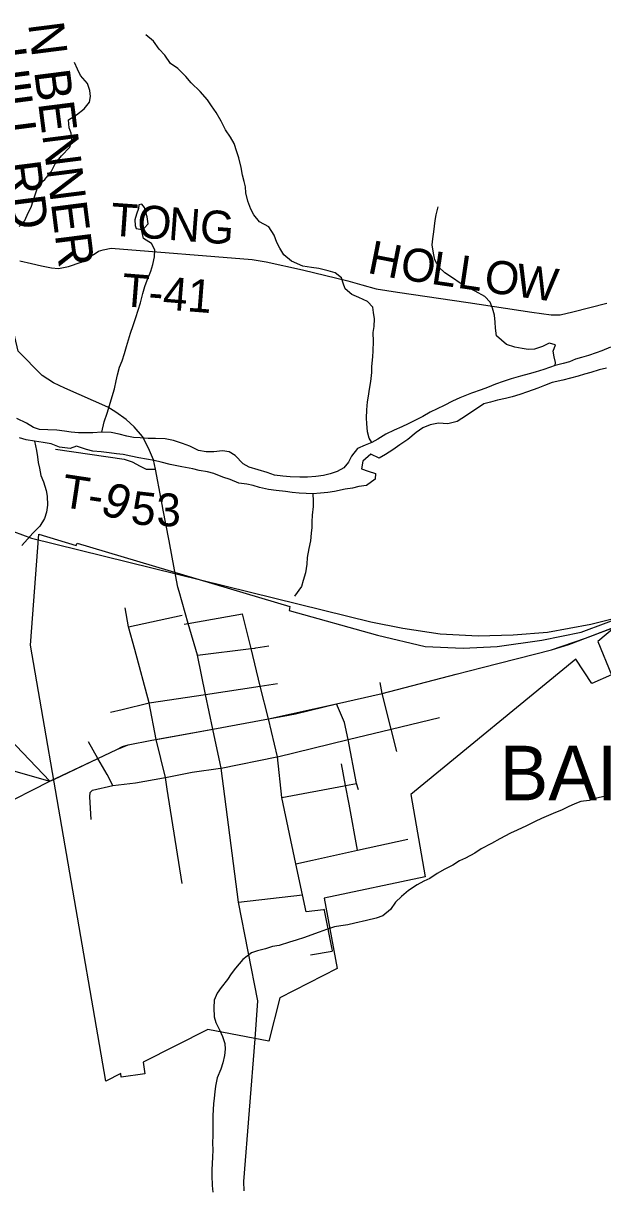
# Model space of a CAD drawing. Extents: x -139 to 835, y 0 to 440.
# Drawn here: x 462.8 to 494.5, y 270.4 to 334.2 of the extents above; entities that cross this region are included whole.
import ezdxf

# ---------------------------------------------------------------- set-up
doc = ezdxf.new("R2010")
doc.units = 0
for name, color, linetype in [('Default', 7, 'Continuous'), ('GM_X_City_Street', 7, 'Continuous'), ('GM_X_Corporation', 7, 'Continuous'), ('GM_X_Corporation_Text', 7, 'Continuous'), ('GM_X_County_Road', 7, 'Continuous'), ('GM_X_Major_River', 7, 'Continuous'), ('GM_X_Minor_Lake', 7, 'Continuous'), ('GM_X_Minor_River', 7, 'Continuous'), ('GM_X_Rail_Line', 7, 'Continuous'), ('GM_X_State_Route', 7, 'Continuous'), ('GM_X_Township_Road', 7, 'Continuous'), ('GM_X_Township_Road_Text', 7, 'Continuous'), ('GM_X_US_Route', 7, 'Continuous'), ('SH_Text', 7, 'Continuous')]:
    doc.layers.add(name, color=color, linetype=linetype)

msp = doc.modelspace()

# ---------------------------------------------------------------- linework, layer by layer
at = {"layer": 'Default'}
for p, q in [((493.599, 300.491), (496.955, 301.767)), ((491.732, 299.847), (493.599, 300.491)), ((493.599, 300.491), (493.599, 300.491)), ((487.937, 298.879), (491.732, 299.847)), ((482.445, 297.453), (486.513, 298.509)), ((486.513, 298.509), (487.937, 298.879)), ((479.94, 296.881), (482.445, 297.453)), ((476.205, 296.063), (479.94, 296.881)), ((473.155, 295.495), (476.205, 296.063)), ((469.81, 294.894), (473.155, 295.495)), ((467.886, 294.389), (468.504, 294.643)), ((468.504, 294.643), (469.81, 294.894)), ((464.221, 292.642), (466.851, 293.897)), ((466.851, 293.897), (467.886, 294.389))]:
    msp.add_line(p, q, dxfattribs=at)
at = {"layer": 'GM_X_City_Street'}
for p, q in [((468.537, 301.111), (471.478, 301.759)), ((475.525, 299.955), (476.231, 300.065)), ((467.542, 296.424), (468.186, 296.579)), ((473.56, 293.615), (473.155, 295.495)), ((471.468, 287.037), (470.652, 292.215)), ((481.092, 288.858), (480.628, 291.386)), ((477.71, 288.118), (478.632, 288.32)), ((474.568, 286.013), (478.072, 286.417)), ((478.272, 285.474), (478.072, 286.417))]:
    msp.add_line(p, q, dxfattribs=at)
for points in [[(468.873, 299.87), (468.537, 301.111), (468.354, 302.157)], [(471.591, 301.266), (471.811, 301.304), (474.792, 301.82)], [(478.072, 286.417), (477.71, 288.118), (476.934, 291.761), (476.699, 293.979), (476.205, 296.063), (475.762, 297.866), (475.258, 299.92), (474.792, 301.82)], [(470.652, 292.215), (470.552, 292.848), (470.045, 294.939), (469.666, 296.937), (468.873, 299.87)], [(472.311, 299.562), (475.258, 299.92), (475.454, 299.944), (475.525, 299.955)], [(468.186, 296.579), (469.666, 296.937), (472.758, 297.408), (475.762, 297.866), (476.702, 298.01)], [(483.245, 294.283), (482.939, 295.497), (482.445, 297.453), (482.331, 298.06)], [(481.151, 292.168), (481.047, 292.517), (480.588, 294.932), (480.385, 295.865), (479.94, 296.881)], [(473.58, 293.36), (473.615, 293.364), (476.677, 293.974), (476.699, 293.979), (480.588, 294.932), (482.939, 295.497), (485.586, 296.134)], [(466.482, 290.547), (466.41, 291.781), (466.42, 292.027), (466.549, 292.154), (467.674, 292.408), (467.36, 293.009), (466.851, 293.897), (466.327, 294.812)], [(470.449, 292.829), (470.552, 292.848), (472.028, 293.144), (473.58, 293.36)], [(475.472, 278.515), (475.617, 280.609), (474.568, 286.013), (473.615, 293.364), (473.56, 293.615)], [(480.628, 291.386), (480.441, 292.405), (480.222, 293.598)], [(467.674, 292.408), (468.907, 292.55), (470.449, 292.829)], [(476.934, 291.761), (480.361, 292.391), (480.441, 292.405), (481.047, 292.517)], [(478.632, 288.32), (481.092, 288.858), (483.86, 289.463)], [(478.508, 283.13), (479.702, 283.33), (479.72, 283.36), (479.706, 283.429), (479.306, 285.472), (479.286, 285.576), (479.272, 285.605), (479.235, 285.6), (478.272, 285.474)]]:
    msp.add_lwpolyline(points, dxfattribs=at)
at = {"layer": 'GM_X_Corporation'}
msp.add_lwpolyline([(472.881, 279.036), (469.327, 277.229), (469.425, 276.595), (468.135, 276.408), (468.104, 276.611), (467.284, 276.194), (463.155, 300.109), (463.618, 306.188), (465.65, 305.582), (465.706, 305.704), (477.378, 302.223), (477.35, 302.012), (482.189, 300.655), (484.807, 300.027), (486.895, 299.935), (488.75, 300.036), (491.21, 300.383), (493.37, 300.818), (496.112, 301.837), (494.271, 300.317), (495.033, 298.472), (493.952, 298.002), (493.067, 299.334), (484.022, 291.91), (484.801, 287.395), (479.266, 286.223), (479.982, 282.368), (476.832, 280.77), (476.231, 278.382)], close=True, dxfattribs=at)
at = {"layer": 'GM_X_County_Road'}
msp.add_lwpolyline([(474.878, 270.188), (474.866, 270.692), (475.472, 278.515)], dxfattribs=at)
at = {"layer": 'GM_X_Major_River'}
for points in [[(494.98, 316.457), (494.507, 316.258), (494.179, 316.142), (493.759, 315.99), (493.379, 315.886), (493.051, 315.794), (492.723, 315.653), (492.369, 315.561), (491.937, 315.446), (491.32, 315.225), (490.847, 315.074), (490.52, 314.982), (490.035, 314.867), (489.524, 314.716), (489.091, 314.565), (488.671, 314.414), (488.224, 314.239), (487.883, 314.11), (487.345, 313.924), (486.715, 313.679), (486.307, 313.492), (485.847, 313.257), (485.084, 312.881), (484.676, 312.645), (484.308, 312.457), (483.874, 312.246), (483.533, 312.082), (483.099, 311.895), (482.652, 311.683), (482.217, 311.412), (481.875, 311.224), (481.521, 311.084), (481.087, 310.897), (480.768, 310.48), (480.607, 310.146), (480.341, 309.837), (479.973, 309.637), (479.592, 309.497), (479.225, 309.417), (478.807, 309.349), (478.349, 309.33), (477.931, 309.323), (477.396, 309.341), (477.005, 309.369), (476.536, 309.434), (476.146, 309.583), (475.639, 309.72), (475.158, 309.869), (474.821, 310.053), (474.383, 310.502), (474.046, 310.71), (473.681, 310.762), (473.211, 310.707)], [(494.755, 315.295), (494.349, 315.204), (493.89, 315.065), (493.549, 314.972), (493.195, 314.856), (492.776, 314.753), (492.356, 314.637), (491.78, 314.512), (491.347, 314.348), (490.979, 314.208), (490.415, 313.999), (489.995, 313.859), (489.575, 313.732), (489.208, 313.64), (488.776, 313.536), (488.383, 313.433), (488.029, 313.341), (487.067, 312.703)], [(473.211, 310.707), (472.793, 310.711), (472.363, 310.776), (471.896, 311.021), (471.493, 311.17), (470.999, 311.331), (470.544, 311.42), (470.008, 311.438), (469.604, 311.443), (469.173, 311.471), (468.808, 311.499), (468.43, 311.575), (468.027, 311.688), (467.584, 311.765), (467.075, 311.782), (466.579, 311.752), (466.134, 311.745), (465.795, 311.748), (465.378, 311.789), (465.013, 311.853), (464.596, 311.906), (464.1, 311.911), (463.656, 311.928), (463.318, 312.052), (462.93, 312.284), (462.411, 312.542)], [(487.067, 312.703), (486.566, 312.373), (486.042, 312.246), (485.546, 312.276), (485.088, 312.185), (484.681, 312.033), (484.312, 311.773), (483.849, 311.394), (483.414, 311.087), (483.032, 310.815), (482.637, 310.567), (482.281, 310.367), (481.827, 310.576), (481.378, 310.197), (481.307, 309.778), (481.671, 309.642), (482.074, 309.53), (482.069, 309.206), (481.581, 308.863), (481.176, 308.807), (480.822, 308.727), (480.417, 308.672), (479.84, 308.534), (479.461, 308.478), (479.068, 308.446), (478.65, 308.415), (478.285, 308.431), (477.893, 308.447), (477.515, 308.475), (477.137, 308.528), (476.628, 308.581), (476.211, 308.646), (475.717, 308.759), (475.366, 308.871), (475.014, 308.935), (474.584, 309), (474.117, 309.185), (473.714, 309.321), (473.207, 309.519), (472.869, 309.607), (472.413, 309.684), (472.062, 309.771), (471.462, 309.886), (470.811, 310.025), (470.317, 310.139), (469.939, 310.227), (469.523, 310.303), (469.093, 310.38), (468.663, 310.481), (468.233, 310.558), (467.869, 310.61), (467.464, 310.65), (467.034, 310.703), (466.578, 310.756), (466.226, 310.844), (465.68, 311.018), (465.326, 310.901), (464.753, 310.968), (464.285, 311.153), (463.855, 311.23), (463.373, 311.295), (462.917, 311.372), (462.553, 311.472)]]:
    msp.add_lwpolyline(points, dxfattribs=at)
at = {"layer": 'GM_X_Minor_Lake'}
for points in [[(469.24, 322.908), (469.411, 323.002), (469.61, 323.216), (469.563, 323.6), (469.475, 323.841), (469.401, 324.118), (469.26, 324.3), (469.089, 324.266), (469.073, 324.05), (468.965, 323.739), (468.869, 323.428), (468.891, 323.128), (468.954, 322.959), (469.058, 322.946)], [(469.058, 322.946), (469.24, 322.908)]]:
    msp.add_lwpolyline(points, dxfattribs=at)
at = {"layer": 'GM_X_Minor_River'}
for points in [[(481.875, 311.224), (481.735, 311.465), (481.648, 311.802), (481.602, 312.259), (481.593, 312.559), (481.6, 313.015), (481.645, 313.447), (481.702, 313.77), (481.746, 314.142), (481.83, 314.573), (481.876, 315.064), (481.881, 315.4), (481.927, 315.916), (481.958, 316.252), (481.965, 316.768), (481.959, 317.248), (482.003, 317.583), (482.035, 318.003), (481.974, 318.352), (481.926, 318.652), (481.643, 318.955), (481.163, 319.177), (480.774, 319.349), (480.425, 319.653), (480.312, 319.954), (480.225, 320.255), (479.863, 320.535), (479.486, 320.647), (478.965, 320.761), (478.561, 320.825), (478.092, 320.902), (477.469, 321.173), (477.056, 321.514), (476.826, 321.888), (476.66, 322.19), (476.522, 322.588), (476.228, 323.059), (475.71, 323.317), (475.402, 323.704), (475.236, 324.018), (475.086, 324.464), (474.974, 324.909), (474.94, 325.245), (474.879, 325.546), (474.792, 325.883), (474.707, 326.304), (474.583, 326.834), (474.47, 327.171), (474.333, 327.616), (474.129, 327.967), (473.86, 328.378), (473.619, 328.848), (473.338, 329.32), (473.082, 329.694), (472.865, 330.021), (472.466, 330.481), (471.976, 330.943), (471.681, 331.294), (471.243, 331.731), (470.842, 332.011), (470.522, 332.459), (470.213, 332.798), (469.893, 333.234), (469.48, 333.574)], [(462.531, 323.077), (462.836, 323.398), (463.024, 323.828), (463.198, 324.138), (463.308, 324.485), (463.43, 324.856), (463.594, 325.346), (463.938, 325.654), (464.296, 326.07), (464.498, 326.512), (464.856, 326.94), (465.307, 327.427), (465.417, 327.822), (465.383, 328.183), (465.283, 328.484), (465.237, 328.928), (465.671, 329.2), (466.094, 329.519), (466.399, 329.888), (466.442, 330.199), (466.408, 330.536), (466.283, 330.921), (465.897, 331.357), (465.732, 331.695), (465.567, 332.069)], [(491.937, 315.446), (491.952, 315.614), (491.878, 315.927), (491.83, 316.227), (491.965, 316.574), (491.601, 316.662), (491.246, 316.486), (490.813, 316.334), (490.46, 316.326), (490.121, 316.378), (489.717, 316.454), (489.275, 316.591), (488.721, 317.078), (488.661, 317.486), (488.653, 317.822), (488.606, 318.207), (488.507, 318.592), (488.368, 318.918), (488.071, 319.233), (487.553, 319.515), (487.125, 319.747), (486.724, 319.968), (486.31, 320.248), (485.883, 320.529), (485.56, 320.833), (485.344, 321.243), (485.258, 321.616), (485.199, 322.073), (485.229, 322.384), (485.287, 322.78), (485.317, 323.091), (485.348, 323.391), (485.405, 323.715), (485.515, 324.145)], [(467.075, 311.782), (467.201, 312.357), (467.351, 312.835), (467.487, 313.254), (467.638, 313.744), (467.761, 314.175), (467.846, 314.606), (467.928, 314.941), (468.039, 315.36), (468.174, 315.707), (468.31, 316.101), (468.42, 316.496), (468.639, 317.214), (468.789, 317.644), (468.938, 318.075), (469.185, 318.888), (469.309, 319.403), (469.432, 319.773), (469.554, 320.132), (469.757, 320.622), (469.866, 320.981), (469.951, 321.4), (469.982, 321.784), (469.791, 322.146), (469.351, 322.415), (469.24, 322.908)], [(463.373, 311.295), (463.484, 310.79), (463.531, 310.441), (463.566, 310.117), (463.64, 309.816), (463.712, 309.407), (463.864, 309.069), (464.015, 308.588), (464.062, 308.275), (464.082, 307.783), (464.037, 307.399), (463.928, 307.053), (463.661, 306.635), (463.277, 306.244), (462.985, 305.923), (462.68, 305.578)], [(478.65, 308.415), (478.658, 308.019), (478.653, 307.707), (478.608, 307.239), (478.59, 306.879), (478.585, 306.568), (478.555, 306.256), (478.51, 305.824), (478.426, 305.417), (478.34, 304.914), (478.309, 304.542), (478.237, 304.075), (478.114, 303.656), (478.018, 303.321), (477.632, 302.786)], [(494.625, 291.798), (494.206, 291.719), (493.812, 291.579), (493.342, 291.524), (493.014, 291.408), (492.658, 291.232), (492.317, 291.067), (491.831, 290.869), (491.187, 290.6), (490.832, 290.435), (490.359, 290.189), (489.86, 289.966), (489.492, 289.79), (488.9, 289.485), (488.439, 289.238), (487.886, 288.932), (487.531, 288.708), (487.018, 288.425), (486.689, 288.273), (486.333, 288.049), (485.886, 287.813), (485.465, 287.59), (485.056, 287.307), (484.728, 287.166), (484.373, 286.966), (483.885, 286.647), (483.515, 286.315), (483.184, 286.007), (482.905, 285.614), (482.482, 285.259), (482.115, 285.143), (481.59, 285.004), (480.949, 284.855), (480.556, 284.776), (480.176, 284.708), (479.836, 284.652), (479.39, 284.513), (478.983, 284.361), (478.537, 284.21), (478.195, 284.07), (477.723, 283.919), (477.356, 283.815), (476.792, 283.641)], [(476.792, 283.641), (476.439, 283.573), (476.046, 283.457), (475.6, 283.342), (475.272, 283.238), (474.797, 282.871), (474.399, 282.395), (474.159, 282.074), (473.959, 281.764), (473.614, 281.336), (473.387, 281.014), (473.225, 280.644), (473.219, 280.212), (473.239, 279.72), (473.313, 279.419), (473.516, 279.009), (473.694, 278.647), (473.819, 278.262), (473.828, 277.949), (473.797, 277.602), (473.713, 277.195), (473.604, 276.86), (473.401, 276.37), (473.304, 275.915), (473.273, 275.603), (473.229, 275.256), (473.199, 274.944), (473.182, 274.644), (473.164, 274.284), (473.149, 273.217), (473.13, 272.809), (473.151, 272.401), (473.146, 272.053), (473.127, 271.657), (473.11, 271.345), (473.106, 271.021), (473.124, 270.469), (473.158, 270.108)]]:
    msp.add_lwpolyline(points, dxfattribs=at)
at = {"layer": 'GM_X_Rail_Line'}
msp.add_lwpolyline([(461.72, 306.518), (463.204, 305.984), (481.829, 301.388), (483.589, 301.041), (485.626, 300.734), (487.707, 300.627), (489.642, 300.667), (491.519, 300.827), (493.891, 301.254), (496.306, 301.869), (510.606, 306.801), (564.86, 326.817)], dxfattribs=at)
at = {"layer": 'GM_X_State_Route'}
msp.add_line((460.922, 290.981), (464.221, 292.642), dxfattribs=at)
for points in [[(470.418, 307.606), (470.395, 307.727), (470.323, 308.109), (470.008, 309.755), (469.895, 310.275), (469.623, 310.919), (469.294, 311.543), (468.841, 312.084), (468.399, 312.489), (467.833, 312.895), (467.402, 313.155), (465.045, 314.194), (464.422, 314.496), (463.798, 314.891), (462.469, 316.225), (462.04, 318.107), (461.936, 318.695)], [(471.114, 303.959), (471.061, 304.235), (470.759, 305.821), (470.418, 307.606)], [(471.311, 303.043), (471.242, 303.283), (471.114, 303.959)], [(473.155, 295.495), (472.758, 297.408), (472.311, 299.562), (471.811, 301.304), (471.311, 303.043)], [(469.81, 294.894), (470.045, 294.939), (473.155, 295.495)], [(464.221, 292.642), (464.431, 292.747), (466.851, 293.897), (467.886, 294.389), (468.209, 294.549), (468.504, 294.643), (469.81, 294.894)]]:
    msp.add_lwpolyline(points, dxfattribs=at)
at = {"layer": 'GM_X_Township_Road'}
for points in [[(462.568, 321.181), (463.204, 321.035), (463.763, 320.914), (464.308, 320.794), (464.686, 320.761), (465.238, 320.88), (465.925, 321.117), (466.35, 321.383), (466.695, 321.58), (466.882, 321.708), (467.146, 321.798), (467.579, 321.872), (475.323, 321.253), (476.078, 321.14), (478.078, 320.687), (480.557, 320.091), (481.334, 319.869), (482.113, 319.659), (483.296, 319.465), (487.174, 318.897), (490.662, 318.374), (491.716, 318.23), (492.212, 318.219), (492.909, 318.383), (494.765, 318.869)], [(464.524, 310.857), (468.286, 310.317), (468.728, 310.171), (469.17, 309.921), (469.498, 309.755), (470.008, 309.755)]]:
    msp.add_lwpolyline(points, dxfattribs=at)
at = {"layer": 'GM_X_US_Route'}
msp.add_line((460.922, 290.981), (464.221, 292.642), dxfattribs=at)
for points in [[(493.599, 300.491), (496.955, 301.767), (497.834, 302.1)], [(486.513, 298.509), (487.937, 298.879), (491.732, 299.847), (492.687, 300.144), (493.599, 300.491)], [(477.313, 296.272), (477.694, 296.343), (479.94, 296.881), (482.445, 297.453), (486.513, 298.509)], [(473.155, 295.495), (476.205, 296.063), (477.313, 296.272)], [(469.81, 294.894), (470.045, 294.939), (473.155, 295.495)], [(464.221, 292.642), (464.431, 292.747), (466.851, 293.897), (467.886, 294.389), (468.209, 294.549), (468.504, 294.643), (469.81, 294.894)]]:
    msp.add_lwpolyline(points, dxfattribs=at)
at = {"layer": 'SH_Text'}
msp.add_lwpolyline([(464.221, 292.642), (447.929, 309.729), (447.761, 297.325)], close=True, dxfattribs=at)

# ---------------------------------------------------------------- texts
at = {"layer": 'GM_X_Corporation_Text'}
msp.add_text('BAINBRIDGE', height=2.9942, rotation=0.00001, dxfattribs=at).set_placement((488.893, 291.598))
at = {"layer": 'GM_X_Township_Road_Text'}
for s, height, rotation, p in [('N BENNER', 1.9603, 277.25481, (463.019, 334.181)), ('HILL RD', 1.9603, 277.28492, (460.944, 332.782)), ('T', 1.801, 355.90953, (467.499, 322.577)), ('O', 1.801, 355.66563, (468.957, 322.473)), ('N', 1.801, 355.66786, (470.674, 322.343)), ('G', 1.801, 355.66786, (472.392, 322.213)), ('H', 1.826, 348.81828, (481.582, 320.535)), ('O', 1.814, 351.5518, (483.375, 320.184)), ('L', 1.814, 351.58248, (485.077, 319.931)), ('L', 1.814, 351.58241, (486.523, 319.717)), ('O', 1.814, 351.578, (487.969, 319.503)), ('W', 1.812, 352.12399, (489.692, 319.248)), ('T-41', 1.8017, 355.46685, (468.108, 318.71)), ('T', 1.815, 351.3903, (464.774, 307.7)), ('9', 1.892, 337.40675, (466.884, 307.397)), ('5', 1.807, 353.46095, (468.6, 306.78)), ('-', 1.815, 351.42687, (466.221, 307.481)), ('3', 1.796, 0.12138, (470.067, 306.628))]:
    msp.add_text(s, height=height, rotation=rotation, dxfattribs=at).set_placement(p)

doc.saveas('drawing.dxf')
